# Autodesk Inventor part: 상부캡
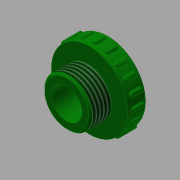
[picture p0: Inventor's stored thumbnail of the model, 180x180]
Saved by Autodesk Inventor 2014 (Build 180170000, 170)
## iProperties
Created: 2015-12
Part Number: 상부캡
Material: PC/ABS 플라스틱
Document SubType Name: Modeling
Designer: mduedu
Density: 7.86 g/cm^3
Appearance: 진녹색
Author: mduedu
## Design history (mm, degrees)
sketch "스케치1"
  geometry: C1 r 12.5 at (0, 0); C2 r 8 at (0, 0); 1 further point
  constraints: 2 centre point, 2 coincident
  dimensions: "d1" = 25 diameter of C1; "d3" = 16 diameter of C2
extrude "돌출1" new body sketch "스케치1" distance "d4" = 12; taper "d6" = 0 deg; dims "d5" = 12, "d7" = 0
sketch "스케치2"
  geometry: C1 r 20 at (0, 0); C2 r 12.5 at (0, 0) reference; 1 further point
  constraints: 1 centre point, 1 coincident
  dimensions: "d8" = 40 diameter of C1
extrude "돌출2" join sketch "스케치2" distance "d10" = 10; taper "d11" = 0 deg
extrude "돌출3" cut sketch "스케치1" stored distance "d34" = 10; taper "d35" = 0 deg
sketch "스케치5"
  geometry: L1 (-20, 0)-(-20, 10) reference; L2 (-20, 10)-(-12.5, 10) reference; L3 (-12.5, 10)-(-12.5, 12) reference; L4 (-12.5, 12)-(12.5, 12) reference; L5 (12.5, 12)-(12.5, 10) reference; L6 (12.5, 10)-(20, 10) reference; L7 (20, 10)-(20, 0) reference; L8 (20, 0)-(12.5, 0) reference; L9 (12.5, 0)-(12.5, -12) reference; L10 (12.5, -12)-(8, -12) reference; L11 (8, -12)-(8, 0) reference; L12 (8, 0)-(-8, 0) reference; L13 (-8, 0)-(-8, -12) reference; L14 (-8, -12)-(-12.5, -12) reference; L15 (-12.5, -12)-(-12.5, 0) reference; L16 (-12.5, 0)-(-20, 0) reference; L17 (12.5, 0)-(10.5, 0); L18 (10.5, 0)-(10.5, -1); L19 (10.5, -1)-(12.5, -1); L20 (12.5, -1)-(12.5, 0); 2 further points
  constraints: 8 end point, 2 parallel, 1 horizontal, 1 midpoint, 1 perpendicular, 1 vertical alignment, 2 other
  dimensions: "d36" = 2 distance of L19.end L18.end; "d37" = 1 distance of L18.end L17.end
revolve "회전1" sketch "스케치5" stored, may be unused: angle "d38" = 90 deg
feature "스레드1" dims "d39" = 10, "d40" = 0
chamfer "모따기3" distance "d41" = 1; stored, may be unused: second distance "d42" = 2, angle "d43" = 45 deg
fillet "모깎기4" dims "d44" = 3
node "작업 평면1"
sketch "스케치7"
  geometry: L1 (1, 0)-(-1, 0); L2 (-1, 0)-(-1, 20.976); L3 (1, 20.976)-(1, 0); C1 r 20 at (0, 0) reference; A1 r 21 centre (0, 0) between (1, 20.976) and (-1, 20.976); 2 further points
  constraints: 6 end point, 2 coincident, 2 point on circle, 1 centre point, 1 horizontal, 1 midpoint, 1 parallel, 1 perpendicular
  dimensions: "d48" = 2 distance of L1.start L1.end; "d49" = 1 radial gap between concentric circles of A1 C1
extrude "돌출4" join sketch "스케치7" distance "d50" = 3; taper "d52" = 0 deg; dims "d51" = 3, "d53" = 0
fillet "모깎기5" dims "d54" = 1
fillet "모깎기6" dims "d55" = 0.5
fillet "모깎기7" dims "d59" = 1
sketch "스케치8"
  geometry: 2 further points
  constraints: 1 coincident, 1 other
feature "엠보싱1" sketch "스케치8" dims "d60" = 0.5, "d61" = 0
node "솔리드1"
pattern_circular "원형 패턴1" dims "d57" = 360 deg
node "절단 모서리 투영1"
node "절단 모서리 투영3"
